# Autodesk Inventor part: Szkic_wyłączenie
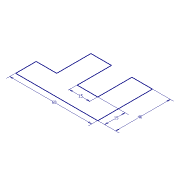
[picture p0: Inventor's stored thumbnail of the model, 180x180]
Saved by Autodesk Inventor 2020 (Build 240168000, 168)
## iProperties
Created: 2015-03
Part Number: Szkic_wyłączenie
Material: Ogólny
Document SubType Name: Modeling
Designer: F.Stasiak
Density: 1 g/cm^3
Appearance: Domyślna
Manager: www.cadconsulting.pl
Company: Fabian Stasiak CAD Consulting
Author: F.Stasiak
Subject: Zbiór ćwiczeń. Autodesk Inventor 2020. Kurs podstawowy
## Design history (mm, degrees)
sketch "Szkic1"
  geometry: L1 (0, 0)-(60, 0); L2 (60, 0)-(60, 40); L3 (60, 40)-(45, 40); L4 (45, 40)-(45, 15); L5 (45, 15)-(30, 15); L6 (15, 15)-(0, 15); L7 (0, 15)-(0, 0); L8 (15, 15)-(15, 40); L9 (15, 40)-(30, 40); L10 (30, 40)-(30, 15)
  constraints: 20 end point, 5 perpendicular, 3 collinear, 2 point on line, 1 horizontal, 1 parallel
  dimensions: "d1" = 15 distance of L4.end L5.end; "d2" = 60 distance of L1.start L1.end; "d3" = 15 distance between parallel lines of L1 L5; "d4" = 40 distance of L1.end L2.end
